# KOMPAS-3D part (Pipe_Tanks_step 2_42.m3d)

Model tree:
1. X Axis
2. Y Axis
3. Z Axis  (labels: Pipe Dn 50; T-Bend Dn 50)
     Òîëùèíà ñòåíêè 1 = 1

Referenced files in C:\Documents and Settings\kashirsky\Мои документы\Camtasia Studio\Pipelines3D\Tanks\: Tanks_step 2.a3d
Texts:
  Pipe Dn 50
  Steel ASTM A295
  Three Point Plane
  Plane at Angle
  Line and Point Plane
  Axis through Two Vertices
  Axis of Feature
  Axis of Conical Surface
  Axis through Edge
  Trim by Surface
  Trim by Sketch
  Feature with No History
  Intersection Axis of Two Planes
  Two Line Plane
  Line and Face Plane
  Bend by line
  Hole in sheet body
  Cut in sheet body
  Point in CM
  Linear Dimension from Line to Point
  Surface Finish Symbol
  Geometric Tolerance Symbol
  Leader #1
  Leader #2
  Leader #3
  Shape Deviations and Datum
  Node point number
  Mark of coordination axis
  Node point designation
  Mark/Reference designation with leader
  Mark/reference designation on line
  Mark/Reference designation without leader
  T-Bend Dn 50
  Plane of section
